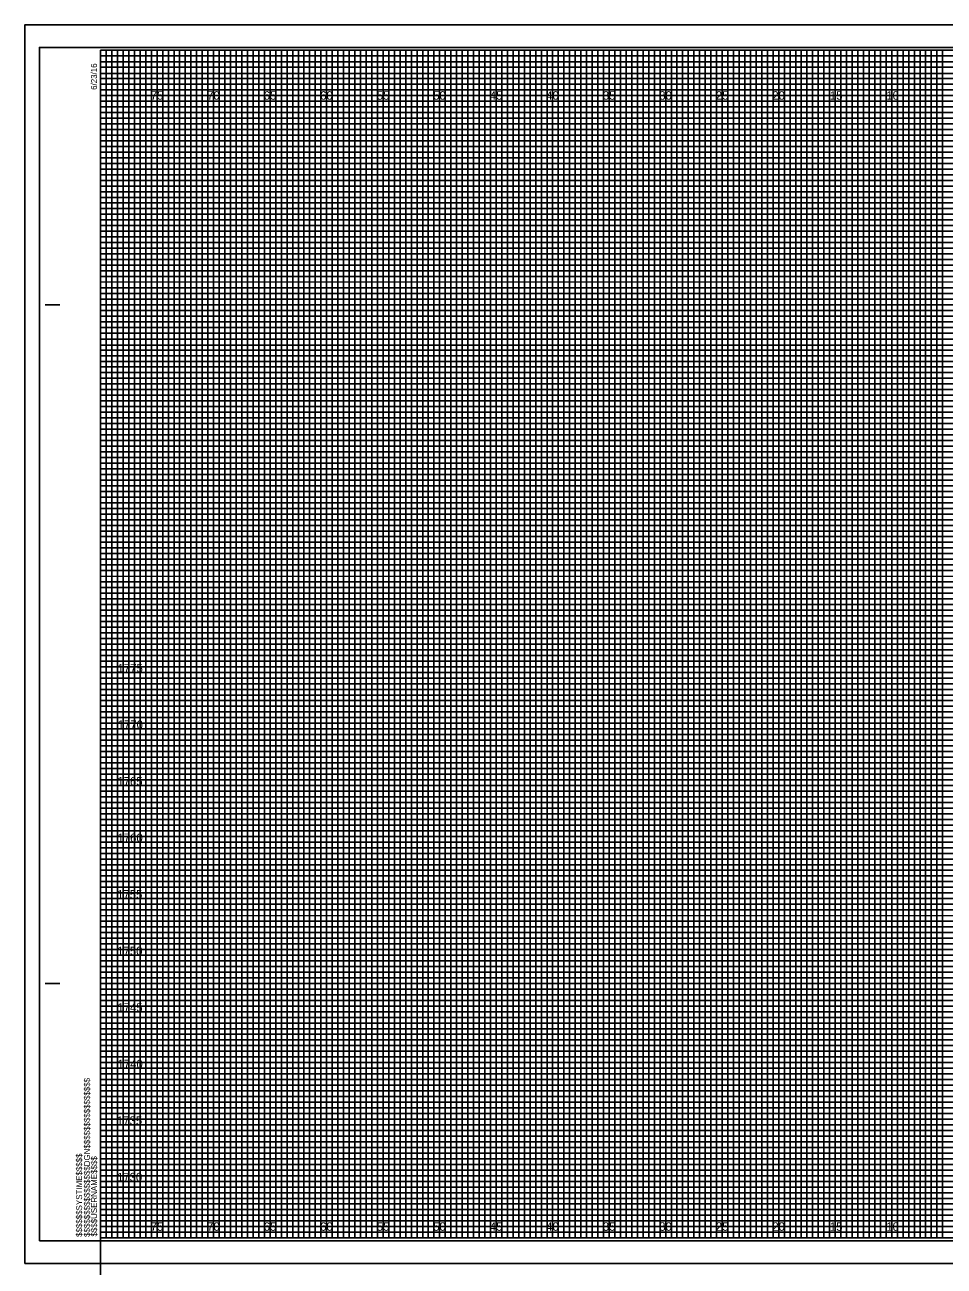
# Model space of a CAD drawing. Extents: x -7 to 392, y -2 to 440.
# Drawn here: x 223.6 to 304.9, y 330.7 to 440.5 of the extents above; entities that cross this region are included whole.
import ezdxf

# ---------------------------------------------------------------- set-up
doc = ezdxf.new("R2010")
doc.units = 0
for name, color, linetype in [('Prop PFL Text', 7, 'Continuous'), ('Prop XS Elevation Labels', 7, 'Continuous'), ('Prop XS Offset Labels', 7, 'Continuous'), ('Sheet Cross Section CELL', 7, 'Continuous'), ('Sheet Cross Section Grid Major CELL', 7, 'Continuous'), ('Sheet Cross Section Grid Middle CELL', 7, 'Continuous'), ('Sheet Cross Section Grid Minor 1 CELL', 7, 'Continuous'), ('Sheet Cross Section Grid Minor 2 CELL', 7, 'Continuous'), ('Sheet Cutting Line CELL', 7, 'Continuous'), ('Sheet DOT Grid CELL', 7, 'Continuous'), ('Sheet Plot Border Inside CELL', 7, 'Continuous'), ('Sheet Plot Border Outside CELL', 7, 'Continuous')]:
    doc.layers.add(name, color=color, linetype=linetype)

msp = doc.modelspace()

# ---------------------------------------------------------------- linework, layer by layer
at = {"layer": 'Prop PFL Text'}
msp.add_line((230.26, 333.21), (230.26, 328.21), dxfattribs=at)
at = {"layer": 'Sheet Cross Section CELL'}
for p, q in [((225.36, 415.71), (226.61, 415.71)), ((225.41, 415.71), (226.66, 415.71)), ((225.36, 355.71), (226.61, 355.71)), ((225.41, 355.71), (226.66, 355.71)), ((230.26, 333.21), (230.26, 333.21)), ((230.26, 333.21), (230.26, 333.21)), ((230.26, 333.21), (230.26, 333.21)), ((230.26, 333.21), (230.26, 333.21)), ((230.26, 333.21), (230.26, 333.21)), ((230.26, 333.21), (230.26, 333.21)), ((230.26, 333.21), (230.26, 333.21))]:
    msp.add_line(p, q, dxfattribs=at)
msp.add_lwpolyline([(390.26, 438.21), (230.26, 438.21), (230.26, 333.21), (390.26, 333.21)], close=True, dxfattribs=at)
at = {"layer": 'Sheet Cross Section Grid Major CELL'}
for p, q in [((235.26, 438.21), (230.26, 438.21)), ((235.26, 333.21), (235.26, 438.21)), ((245.26, 438.21), (240.26, 438.21)), ((240.26, 438.21), (240.26, 333.21)), ((245.26, 333.21), (245.26, 438.21)), ((255.26, 438.21), (250.26, 438.21)), ((250.26, 438.21), (250.26, 333.21)), ((255.26, 333.21), (255.26, 438.21)), ((265.26, 438.21), (260.26, 438.21)), ((260.26, 438.21), (260.26, 333.21)), ((265.26, 333.21), (265.26, 438.21)), ((275.26, 438.21), (270.26, 438.21)), ((270.26, 438.21), (270.26, 333.21)), ((275.26, 333.21), (275.26, 438.21)), ((285.26, 438.21), (280.26, 438.21)), ((280.26, 438.21), (280.26, 333.21)), ((285.26, 333.21), (285.26, 438.21)), ((295.26, 438.21), (290.26, 438.21)), ((290.26, 438.21), (290.26, 333.21)), ((295.26, 333.21), (295.26, 438.21)), ((305.26, 438.21), (300.26, 438.21)), ((300.26, 438.21), (300.26, 333.21)), ((240.26, 333.21), (235.26, 333.21)), ((250.26, 333.21), (245.26, 333.21)), ((260.26, 333.21), (255.26, 333.21)), ((270.26, 333.21), (265.26, 333.21)), ((280.26, 333.21), (275.26, 333.21)), ((290.26, 333.21), (285.26, 333.21)), ((300.26, 333.21), (295.26, 333.21))]:
    msp.add_line(p, q, dxfattribs=at)
for points in [[(230.26, 433.21), (390.26, 433.21), (390.26, 428.21), (230.26, 428.21)], [(230.26, 423.21), (390.26, 423.21), (390.26, 418.21), (230.26, 418.21)], [(230.26, 413.21), (390.26, 413.21), (390.26, 408.21), (230.26, 408.21)], [(230.26, 403.21), (390.26, 403.21), (390.26, 398.21), (230.26, 398.21)], [(230.26, 393.21), (390.26, 393.21), (390.26, 388.21), (230.26, 388.21)], [(230.26, 383.21), (390.26, 383.21), (390.26, 378.21), (230.26, 378.21)], [(230.26, 373.21), (390.26, 373.21), (390.26, 368.21), (230.26, 368.21)], [(230.26, 363.21), (390.26, 363.21), (390.26, 358.21), (230.26, 358.21)], [(230.26, 353.21), (390.26, 353.21), (390.26, 348.21), (230.26, 348.21)], [(230.26, 343.21), (390.26, 343.21), (390.26, 338.21), (230.26, 338.21)]]:
    msp.add_lwpolyline(points, dxfattribs=at)
at = {"layer": 'Sheet Cross Section Grid Middle CELL'}
for points in [[(230.26, 438.21), (232.76, 438.21), (232.76, 333.21), (237.76, 333.21), (237.76, 438.21), (242.76, 438.21), (242.76, 333.21), (247.76, 333.21), (247.76, 438.21), (252.76, 438.21), (252.76, 333.21), (257.76, 333.21), (257.76, 438.21), (262.76, 438.21), (262.76, 333.21), (267.76, 333.21), (267.76, 438.21), (272.76, 438.21), (272.76, 333.21), (277.76, 333.21), (277.76, 438.21), (282.76, 438.21), (282.76, 333.21), (287.76, 333.21), (287.76, 438.21), (292.76, 438.21), (292.76, 333.21), (297.76, 333.21), (297.76, 438.21), (302.76, 438.21), (302.76, 333.21), (307.76, 333.21)], [(230.26, 435.71), (367.76, 435.71)], [(230.26, 425.71), (390.26, 425.71), (390.26, 430.71), (230.26, 430.71)], [(230.26, 415.71), (390.26, 415.71), (390.26, 420.71), (230.26, 420.71)], [(230.26, 405.71), (390.26, 405.71), (390.26, 410.71), (230.26, 410.71)], [(230.26, 395.71), (390.26, 395.71), (390.26, 400.71), (230.26, 400.71)], [(230.26, 385.71), (390.26, 385.71), (390.26, 390.71), (230.26, 390.71)], [(230.26, 375.71), (390.26, 375.71), (390.26, 380.71), (230.26, 380.71)], [(230.26, 365.71), (390.26, 365.71), (390.26, 370.71), (230.26, 370.71)], [(230.26, 355.71), (390.26, 355.71), (390.26, 360.71), (230.26, 360.71)], [(230.26, 345.71), (390.26, 345.71), (390.26, 350.71), (230.26, 350.71)], [(230.26, 335.71), (390.26, 335.71), (390.26, 340.71), (230.26, 340.71)]]:
    msp.add_lwpolyline(points, dxfattribs=at)
at = {"layer": 'Sheet Cross Section Grid Minor 1 CELL'}
for p, q in [((230.26, 437.71), (360.26, 437.71)), ((360.26, 437.2), (230.26, 437.2)), ((230.26, 437.2), (230.26, 436.71)), ((230.26, 436.71), (360.26, 436.71)), ((360.26, 436.16), (230.26, 436.16)), ((230.26, 436.16), (230.26, 435.21)), ((230.26, 435.21), (390.26, 435.21))]:
    msp.add_line(p, q, dxfattribs=at)
for points in [[(230.26, 434.71), (365.26, 434.71), (390.26, 434.71), (390.26, 434.21), (230.26, 434.21)], [(230.26, 433.71), (390.26, 433.71), (390.26, 432.71), (230.26, 432.71)], [(230.26, 432.21), (390.26, 432.21), (390.26, 431.71), (230.26, 431.7)], [(230.26, 431.21), (390.26, 431.21), (390.26, 430.21), (230.26, 430.21)], [(230.26, 429.71), (390.26, 429.71), (390.26, 429.21), (230.26, 429.21)], [(230.26, 428.71), (390.26, 428.71), (390.26, 427.71), (230.26, 427.71)], [(230.26, 427.21), (390.26, 427.21), (390.26, 426.71), (230.26, 426.71)], [(230.26, 426.21), (390.26, 426.21), (390.26, 425.21), (230.26, 425.21)], [(230.26, 424.71), (390.26, 424.71), (390.26, 424.21), (230.26, 424.21)], [(230.26, 423.71), (390.26, 423.71), (390.26, 422.71), (230.26, 422.71)], [(230.26, 422.21), (390.26, 422.21), (390.26, 421.71), (230.26, 421.71)], [(230.26, 421.21), (390.26, 421.21), (390.26, 420.19), (390.26, 419.71), (390.26, 419.21), (230.26, 419.21)], [(230.26, 420.21), (390.26, 420.21), (390.26, 419.71), (230.26, 419.71)], [(230.26, 418.71), (390.26, 418.71), (390.26, 417.71), (230.26, 417.73)], [(230.26, 417.73), (390.26, 417.71), (390.26, 417.21), (230.26, 417.21)], [(230.26, 416.71), (390.26, 416.71), (390.26, 416.21), (230.26, 416.21)], [(230.26, 415.21), (390.26, 415.21), (390.26, 414.71), (230.26, 414.71)], [(230.26, 414.21), (390.26, 414.21), (390.26, 413.71), (230.26, 413.71)], [(230.23, 412.66), (390.26, 412.66), (390.26, 412.15), (230.23, 412.15)], [(230.26, 411.71), (390.26, 411.71), (390.26, 411.21), (230.26, 411.21)], [(230.26, 410.21), (390.26, 410.21), (390.26, 409.71), (230.26, 409.71)], [(230.26, 409.21), (390.26, 409.21), (390.26, 408.71), (230.26, 408.71)], [(230.26, 407.71), (390.26, 407.71), (390.26, 407.21), (230.26, 407.21)], [(230.26, 406.71), (390.26, 406.71), (390.26, 406.21), (230.26, 406.21)], [(230.26, 405.21), (390.26, 405.21), (390.26, 404.71), (230.26, 404.71)], [(230.26, 404.21), (390.26, 404.21), (390.26, 403.71), (230.26, 403.71)], [(230.26, 402.71), (390.26, 402.71), (390.26, 402.2), (230.26, 402.21)], [(230.26, 401.71), (390.26, 401.71), (390.26, 401.21), (230.26, 401.21)], [(230.26, 400.21), (390.26, 400.21), (390.26, 399.71), (230.26, 399.71)], [(230.26, 399.21), (390.26, 399.21), (390.26, 398.71), (230.26, 398.71)], [(230.26, 397.71), (390.26, 397.71), (390.26, 397.21), (230.26, 397.21)], [(230.26, 396.71), (390.26, 396.71), (390.26, 396.21), (230.26, 396.21)], [(230.26, 395.21), (390.26, 395.21), (390.26, 394.71), (230.26, 394.71)], [(230.26, 394.21), (390.26, 394.21), (390.26, 393.71), (230.26, 393.71)], [(230.26, 392.71), (390.26, 392.71), (390.26, 392.21), (230.26, 392.21)], [(230.26, 391.71), (390.3, 391.67), (390.26, 391.21), (230.26, 391.21)], [(230.26, 390.21), (390.26, 390.21), (390.26, 389.71), (230.26, 389.71)], [(230.26, 389.21), (390.26, 389.21), (390.26, 388.71), (230.26, 388.71)], [(230.26, 387.71), (390.26, 387.71), (390.26, 387.21), (230.26, 387.21)], [(230.26, 386.71), (390.26, 386.71), (390.26, 386.21), (230.26, 386.21)], [(230.26, 385.21), (390.26, 385.21), (390.26, 384.71), (230.26, 384.71)], [(230.26, 384.21), (390.26, 384.21), (390.26, 383.71), (230.26, 383.71)], [(230.26, 382.71), (390.26, 382.71), (390.26, 382.21), (230.26, 382.21)], [(230.26, 381.71), (390.26, 381.71), (390.26, 381.21), (230.26, 381.21)], [(230.26, 380.21), (390.26, 380.21), (390.26, 379.71), (230.26, 379.71)], [(230.26, 379.21), (390.26, 379.21), (390.26, 378.71), (230.26, 378.71)], [(230.26, 377.71), (390.26, 377.71), (390.26, 377.21), (230.26, 377.21)], [(230.26, 376.71), (390.26, 376.71), (390.26, 376.21), (230.26, 376.21)], [(230.26, 375.21), (390.26, 375.21), (390.26, 374.71), (230.26, 374.71)], [(230.26, 374.21), (390.26, 374.21), (390.26, 373.71), (230.26, 373.71)], [(230.26, 372.71), (390.26, 372.71), (390.26, 372.2), (230.26, 372.21)], [(230.26, 371.71), (390.26, 371.71), (390.26, 371.21), (230.26, 371.21)], [(230.26, 370.21), (390.26, 370.21), (390.26, 369.71), (230.26, 369.71)], [(230.26, 369.21), (390.26, 369.21), (390.26, 368.71), (230.26, 368.71)], [(230.26, 367.71), (390.26, 367.71), (390.26, 367.21), (230.26, 367.21)], [(230.26, 366.71), (390.26, 366.71), (390.26, 366.21), (230.26, 366.21)], [(230.26, 365.21), (390.26, 365.21), (390.26, 364.71), (230.26, 364.71)], [(230.26, 364.21), (390.26, 364.21), (390.26, 363.71), (230.26, 363.71)], [(230.26, 362.71), (390.26, 362.71), (390.26, 362.21), (230.26, 362.21)], [(230.26, 361.71), (390.3, 361.67), (390.26, 361.21), (230.26, 361.21)], [(230.26, 360.21), (390.26, 360.21), (390.26, 359.71), (230.26, 359.71)], [(230.26, 359.21), (390.26, 359.21), (390.26, 358.71), (230.26, 358.71)], [(230.26, 357.71), (390.26, 357.71), (390.26, 357.21), (230.26, 357.21)], [(230.26, 356.71), (390.26, 356.71), (390.26, 356.21), (230.26, 356.21)], [(230.26, 355.21), (390.26, 355.21), (390.26, 354.71), (230.26, 354.71)], [(230.26, 354.21), (390.26, 354.21), (390.26, 353.71), (230.26, 353.71)], [(230.26, 352.71), (390.26, 352.71), (390.26, 352.21), (230.26, 352.21)], [(230.26, 351.71), (390.26, 351.71), (390.26, 351.21), (230.26, 351.21)], [(230.26, 350.21), (390.26, 350.21), (390.26, 349.71), (230.26, 349.71)], [(230.26, 349.21), (390.26, 349.21), (390.26, 348.71), (230.26, 348.71)], [(230.26, 347.71), (390.26, 347.71), (390.26, 347.21), (230.26, 347.21)], [(230.26, 346.71), (390.26, 346.71), (390.26, 346.21), (230.26, 346.21)], [(230.26, 345.21), (390.26, 345.21), (390.26, 344.71), (230.26, 344.71)], [(230.26, 344.21), (390.26, 344.21), (390.26, 343.71), (230.26, 343.71)], [(230.26, 342.71), (390.26, 342.71), (390.26, 342.21), (230.26, 342.21)], [(230.26, 341.71), (390.26, 341.71), (390.26, 341.21), (230.26, 341.21)], [(230.26, 340.21), (390.26, 340.21), (390.26, 339.71), (230.26, 339.71)], [(230.26, 339.21), (390.26, 339.21), (390.26, 338.71), (230.26, 338.71)], [(230.26, 337.71), (390.26, 337.71), (390.26, 337.21), (230.26, 337.21)], [(230.26, 336.71), (390.26, 336.71), (390.26, 336.21), (230.26, 336.21)], [(230.26, 335.21), (390.26, 335.21), (390.26, 334.71), (230.26, 334.71)], [(230.26, 334.21), (390.26, 334.21), (390.26, 333.71), (230.26, 333.71)]]:
    msp.add_lwpolyline(points, dxfattribs=at)
at = {"layer": 'Sheet Cross Section Grid Minor 2 CELL'}
for points in [[(230.26, 333.21), (230.76, 333.21), (230.76, 438.21), (231.26, 438.21), (231.26, 333.21)], [(231.26, 333.21), (231.76, 333.21), (231.76, 438.21), (232.26, 438.21), (232.26, 333.21)], [(232.76, 333.21), (233.26, 333.21), (233.26, 438.21), (233.76, 438.21), (233.76, 333.21)], [(233.76, 333.21), (234.26, 333.21), (234.26, 438.21), (234.76, 438.21), (234.76, 333.21)], [(235.26, 333.21), (235.76, 333.21), (235.76, 438.21), (236.26, 438.21), (236.26, 333.21)], [(236.26, 333.21), (236.76, 333.21), (236.76, 438.21), (237.26, 438.21), (237.26, 333.21)], [(237.76, 333.21), (238.26, 333.21), (238.26, 438.21), (238.76, 438.21), (238.76, 333.21)], [(238.76, 333.21), (239.26, 333.21), (239.26, 438.21), (239.76, 438.21), (239.76, 333.21)], [(240.26, 333.21), (240.76, 333.21), (240.76, 438.21), (241.26, 438.21), (241.26, 333.21)], [(241.26, 333.21), (241.76, 333.21), (241.76, 438.21), (242.26, 438.21), (242.26, 333.21)], [(242.76, 333.21), (243.26, 333.21), (243.26, 438.21), (243.76, 438.21), (243.76, 333.21)], [(243.76, 333.21), (244.26, 333.21), (244.26, 438.21), (244.76, 438.21), (244.76, 333.21)], [(245.26, 333.21), (245.76, 333.21), (245.76, 438.21), (246.26, 438.21), (246.26, 333.21)], [(246.26, 333.21), (246.76, 333.21), (246.76, 438.21), (247.26, 438.21), (247.26, 333.21)], [(247.76, 333.21), (248.26, 333.21), (248.26, 438.21), (248.76, 438.21), (248.76, 333.21)], [(248.76, 333.21), (249.26, 333.21), (249.26, 438.21), (249.76, 438.21), (249.76, 333.21)], [(250.26, 333.21), (250.76, 333.21), (250.76, 438.21), (251.26, 438.21), (251.26, 333.21)], [(251.26, 333.21), (251.76, 333.21), (251.76, 438.21), (252.26, 438.21), (252.26, 333.21)], [(252.76, 333.21), (253.26, 333.21), (253.26, 438.21), (253.76, 438.21), (253.76, 333.21)], [(253.76, 333.21), (254.26, 333.21), (254.26, 438.21), (254.76, 438.21), (254.76, 333.21)], [(255.26, 333.21), (255.76, 333.21), (255.76, 438.21), (256.26, 438.21), (256.26, 333.21)], [(256.26, 333.21), (256.76, 333.21), (256.76, 438.21), (257.26, 438.21), (257.26, 333.21)], [(257.76, 333.21), (258.26, 333.21), (258.26, 438.21), (258.76, 438.21), (258.76, 333.21)], [(258.76, 333.21), (259.26, 333.21), (259.26, 438.21), (259.76, 438.21), (259.76, 333.21)], [(260.26, 333.21), (260.76, 333.21), (260.76, 438.21), (261.26, 438.21), (261.26, 333.21)], [(261.26, 333.21), (261.76, 333.21), (261.76, 438.21), (262.26, 438.21), (262.26, 333.21)], [(262.76, 333.21), (263.26, 333.21), (263.26, 438.21), (263.76, 438.21), (263.76, 333.21)], [(263.76, 333.21), (264.26, 333.21), (264.26, 438.21), (264.76, 438.21), (264.76, 333.21)], [(265.26, 333.21), (265.76, 333.21), (265.76, 438.21), (266.26, 438.21), (266.26, 333.21)], [(266.26, 333.21), (266.76, 333.21), (266.76, 438.21), (267.26, 438.21), (267.26, 333.21)], [(267.76, 333.21), (268.26, 333.21), (268.26, 438.21), (268.76, 438.21), (268.76, 333.21)], [(268.76, 333.21), (269.26, 333.21), (269.26, 438.21), (269.76, 438.21), (269.76, 333.21)], [(270.26, 333.21), (270.76, 333.21), (270.76, 438.21), (271.26, 438.21), (271.26, 333.21)], [(271.26, 333.21), (271.76, 333.21), (271.76, 438.21), (272.26, 438.21), (272.26, 333.21)], [(272.76, 333.21), (273.26, 333.21), (273.26, 438.21), (273.76, 438.21), (273.76, 333.21)], [(273.76, 333.21), (274.26, 333.21), (274.26, 438.21), (274.76, 438.21), (274.76, 333.21)], [(275.26, 333.21), (275.76, 333.21), (275.76, 438.21), (276.26, 438.21), (276.26, 333.21)], [(276.26, 333.21), (276.76, 333.21), (276.76, 438.21), (277.26, 438.21), (277.26, 333.21)], [(277.76, 333.21), (278.26, 333.21), (278.26, 438.21), (278.76, 438.21), (278.76, 333.21)], [(278.76, 333.21), (279.26, 333.21), (279.26, 438.21), (279.76, 438.21), (279.76, 333.21)], [(280.26, 333.21), (280.76, 333.21), (280.76, 438.21), (281.26, 438.21), (281.26, 333.21)], [(281.26, 333.21), (281.76, 333.21), (281.76, 438.21), (282.26, 438.21), (282.26, 333.21)], [(282.76, 333.21), (283.26, 333.21), (283.26, 438.21), (283.76, 438.21), (283.76, 333.21)], [(283.76, 333.21), (284.26, 333.21), (284.26, 438.21), (284.76, 438.21), (284.76, 333.21)], [(285.26, 333.21), (285.76, 333.21), (285.76, 438.21), (286.26, 438.21), (286.26, 333.21)], [(286.26, 333.21), (286.76, 333.21), (286.76, 438.21), (287.26, 438.21), (287.26, 333.21)], [(287.76, 333.21), (288.26, 333.21), (288.26, 438.21), (288.76, 438.21), (288.76, 333.21)], [(288.76, 333.21), (289.26, 333.21), (289.26, 438.21), (289.76, 438.21), (289.76, 333.21)], [(290.26, 333.21), (290.76, 333.21), (290.76, 438.21), (291.26, 438.21), (291.26, 333.21)], [(291.26, 333.21), (291.76, 333.21), (291.76, 438.21), (292.26, 438.21), (292.26, 333.21)], [(292.76, 333.21), (293.26, 333.21), (293.26, 438.21), (293.76, 438.21), (293.76, 333.21)], [(293.76, 333.21), (294.26, 333.21), (294.26, 438.21), (294.76, 438.21), (294.76, 333.21)], [(295.26, 333.21), (295.76, 333.21), (295.76, 438.21), (296.26, 438.21), (296.26, 333.21)], [(296.26, 333.21), (296.76, 333.21), (296.76, 438.21), (297.26, 438.21), (297.26, 333.21)], [(297.76, 333.21), (298.26, 333.21), (298.26, 438.21), (298.76, 438.21), (298.76, 333.21)], [(298.76, 333.21), (299.26, 333.21), (299.26, 438.21), (299.76, 438.21), (299.76, 333.21)], [(300.26, 333.21), (300.76, 333.21), (300.76, 438.21), (301.26, 438.21), (301.26, 333.21)], [(301.26, 333.21), (301.76, 333.21), (301.76, 438.21), (302.26, 438.21), (302.26, 333.21)], [(302.76, 333.21), (303.26, 333.21), (303.26, 438.21), (303.76, 438.21), (303.76, 333.21)], [(303.76, 333.21), (304.26, 333.21), (304.26, 438.21), (304.76, 438.21), (304.76, 333.21)]]:
    msp.add_lwpolyline(points, dxfattribs=at)
at = {"layer": 'Sheet Cutting Line CELL'}
for p, q in [((391.91, 440.46), (223.56, 440.46)), ((223.56, 440.46), (223.56, 330.96)), ((223.56, 330.96), (391.91, 330.96))]:
    msp.add_line(p, q, dxfattribs=at)
at = {"layer": 'Sheet DOT Grid CELL'}
for p, q in [((235.26, 333.21), (235.26, 438.21)), ((240.26, 333.21), (240.26, 438.21)), ((245.26, 333.21), (245.26, 438.21)), ((250.26, 333.21), (250.26, 438.21)), ((255.26, 333.21), (255.26, 438.21)), ((260.26, 333.21), (260.26, 438.21)), ((265.26, 333.21), (265.26, 438.21)), ((270.26, 333.21), (270.26, 438.21)), ((275.26, 333.21), (275.26, 438.21)), ((280.26, 333.21), (280.26, 438.21)), ((285.26, 333.21), (285.26, 438.21)), ((290.26, 333.21), (290.26, 438.21)), ((295.26, 333.21), (295.26, 438.21)), ((300.26, 333.21), (300.26, 438.21)), ((230.26, 433.21), (390.26, 433.21)), ((230.26, 428.21), (390.26, 428.21)), ((230.26, 423.21), (390.26, 423.21)), ((230.26, 418.21), (390.26, 418.21)), ((230.26, 413.21), (390.26, 413.21)), ((230.26, 408.21), (390.26, 408.21)), ((230.26, 403.21), (390.26, 403.21)), ((230.26, 398.21), (390.26, 398.21)), ((230.26, 393.21), (390.26, 393.21)), ((230.26, 388.21), (390.26, 388.21)), ((230.26, 383.21), (390.26, 383.21)), ((230.26, 378.21), (390.26, 378.21)), ((230.26, 373.21), (390.26, 373.21)), ((230.26, 368.21), (390.26, 368.21)), ((230.26, 363.21), (390.26, 363.21)), ((230.26, 358.21), (390.26, 358.21)), ((230.26, 353.21), (390.26, 353.21)), ((230.26, 348.21), (390.26, 348.21)), ((230.26, 343.21), (390.26, 343.21)), ((230.26, 338.21), (390.26, 338.21))]:
    msp.add_line(p, q, dxfattribs=at)
at = {"layer": 'Sheet Plot Border Inside CELL'}
msp.add_lwpolyline([(224.86, 332.96), (391.46, 332.96), (391.46, 438.46), (224.86, 438.46)], close=True, dxfattribs=at)
at = {"layer": 'Sheet Plot Border Outside CELL'}
msp.add_lwpolyline([(223.56, 330.96), (391.91, 330.96), (391.91, 440.46), (223.56, 440.46)], close=True, dxfattribs=at)

# ---------------------------------------------------------------- texts
at = {"layer": 'Prop XS Elevation Labels'}
for s, p in [('1775', (231.77, 383.21)), ('1770', (231.78, 378.21)), ('1765', (231.75, 373.21)), ('1760', (231.76, 368.21)), ('1755', (231.73, 363.21)), ('1750', (231.74, 358.21)), ('1745', (231.75, 353.21)), ('1740', (231.76, 348.21)), ('1735', (231.71, 343.21)), ('1730', (231.72, 338.21))]:
    msp.add_text(s, height=0.75, dxfattribs=at).set_placement(p)
at = {"layer": 'Prop XS Offset Labels'}
for s, p in [('75', (234.7, 433.84)), ('70', (239.69, 433.84)), ('65', (244.7, 433.84)), ('60', (249.69, 433.84)), ('55', (254.7, 433.84)), ('50', (259.69, 433.84)), ('45', (264.7, 433.84)), ('40', (269.69, 433.84)), ('35', (274.7, 433.84)), ('30', (279.69, 433.84)), ('25', (284.7, 433.84)), ('20', (289.69, 433.84)), ('15', (294.79, 433.84)), ('10', (299.78, 433.84)), ('75', (234.7, 333.84)), ('70', (239.69, 333.84)), ('65', (244.7, 333.84)), ('60', (249.69, 333.84)), ('55', (254.7, 333.84)), ('50', (259.69, 333.84)), ('45', (264.7, 333.84)), ('40', (269.69, 333.84)), ('35', (274.7, 333.84)), ('30', (279.69, 333.84)), ('25', (284.7, 333.84)), ('20', (289.69, 333.84)), ('15', (294.79, 333.84)), ('10', (299.78, 333.84))]:
    msp.add_text(s, height=0.75, dxfattribs=at).set_placement(p)
at = {"layer": 'Sheet Cross Section CELL'}
for s, p in [('6/23/16', (229.94, 434.71)), ('$$$$$$$$$$$$$$$$DGN$$$$$$$$$$$$$$$$', (229.32, 333.3)), ('$$$$$$SYSTIME$$$$$', (228.63, 333.3)), ('$$$$USERNAME$$$$', (229.95, 333.33))]:
    msp.add_text(s, height=0.525, rotation=90, dxfattribs=at).set_placement(p)

doc.saveas('drawing.dxf')
